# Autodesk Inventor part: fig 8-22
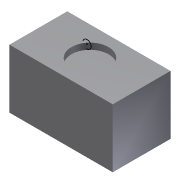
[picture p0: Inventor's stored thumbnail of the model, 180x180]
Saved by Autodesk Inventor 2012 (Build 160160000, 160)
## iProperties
Created: 2011-07
Part Number: fig 8-22
Material: Default
Document SubType Name: Modeling
Designer: CadCim
Density: 1 g/cm^3
Author: CadCim
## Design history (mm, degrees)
sketch "Sketch1"
  geometry: L1 (-18, 10)-(7, 10); L2 (7, 10)-(7, -4); L3 (7, -4)-(-18, -4); L4 (-18, -4)-(-18, 10); 1 further point
  constraints: 8 end point, 2 parallel, 1 horizontal, 1 perpendicular
extrude "Extrusion1" new body sketch "Sketch1" distance "d0" = 14.25; taper "d1" = 0 deg
sketch "Sketch2"
  geometry: C1 r 4.5 at (-5.5, 3); 1 further point
  constraints: 1 centre point
extrude "Extrusion2" cut sketch "Sketch2" distance "d2" = 1.5; taper "d3" = 0 deg
workplane "Work Plane2"
sketch "Sketch4"
  geometry: C1 r 1 at (9, -14); 1 further point
  constraints: 1 centre point
body "Solid1"
other parameters: "d4" = -4.25
